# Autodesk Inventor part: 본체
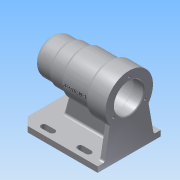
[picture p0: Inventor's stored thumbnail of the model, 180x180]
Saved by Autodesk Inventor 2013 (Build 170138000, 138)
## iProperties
Created: 2017-09
Part Number: 본체
Material: 알루미늄 6061
Document SubType Name: Modeling
Designer: Administrator
Mass: 702.292 g
Surface Area: 713.068 cm^2
Volume: 259.148 cm^3
Density: 2.71 g/cm^3
Author: Administrator
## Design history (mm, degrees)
node "스케치1"
sketch "스케치2"
  geometry: C1 r 34 at (0, 0); 1 further point
  constraints: 1 centre point, 1 coincident
  dimensions: "d15" = 68 diameter of C1
extrude "돌출1" new body sketch "스케치2" distance "d17" = 28; taper "d18" = 0 deg
sketch "스케치3"
  geometry: C1 r 34 at (0, 0) reference; C2 r 30 at (0, 0)
  constraints: 1 centre point, 1 coincident
  dimensions: "d19" = 60 diameter of C2
extrude "돌출2" join sketch "스케치3" distance "d21" = 39; taper "d22" = 0 deg
sketch "스케치4"
  geometry: C1 r 30 at (0, 0) reference; C2 r 27 at (0, 0)
  constraints: 1 centre point, 1 coincident
  dimensions: "d23" = 54 diameter of C2
extrude "돌출3" join sketch "스케치4" distance "d25" = 20; taper "d26" = 0 deg
sketch "스케치5"
  geometry: C1 r 27 at (0, 0) reference; C2 r 25 at (0, 0)
  constraints: 1 centre point, 1 coincident
  dimensions: "d27" = 50 diameter of C2
extrude "돌출4" join sketch "스케치5" distance "d29" = 25; taper "d30" = 0 deg
sketch "스케치6"
  geometry: C1 r 34 at (0, 0) reference; 1 further point
  constraints: 1 coincident
hole "구멍1" sketch "스케치6" at (0, 0) diameter "d31" = 42; stored, may be unused: countersink angle "d35" = 90 deg, drill point angle "d37" = 0 deg; dims "d32" = 6, "d33" = 42, "d34" = 15, "d36" = 15
sketch "스케치7"
  geometry: C1 r 21 at (0, 0) reference
sketch "스케치8"
  geometry: C1 r 21 at (0, 0) reference; C2 r 24 at (0, 0)
  constraints: 2 coincident, 1 centre point
  dimensions: "d38" = 48 diameter of C2
extrude "돌출5" cut sketch "스케치8" distance "d40" = 54; taper "d41" = 0 deg
sketch "스케치9"
  geometry: C1 r 24 at (0, 0) reference; C2 r 21 at (0, 0)
  constraints: 1 centre point, 1 coincident
  dimensions: "d42" = 42 diameter of C2
extrude "돌출6" cut sketch "스케치9" distance "d44" = 12; taper "d45" = 0 deg
sketch "스케치10"
  geometry: C1 r 21 at (0, 0) reference; C2 r 17.5 at (0, 0)
  constraints: 1 centre point, 1 coincident
  dimensions: "d46" = 35 diameter of C2
extrude "돌출7" cut sketch "스케치10" distance "d48" = 18; taper "d49" = 0 deg
sketch "스케치11"
  geometry: C1 r 17.5 at (0, 0) reference; C2 r 16 at (0, 0)
  constraints: 1 centre point, 1 coincident
  dimensions: "d50" = 32 diameter of C2
extrude "돌출8" cut sketch "스케치11" distance "d52" = 4; taper "d53" = 0 deg
sketch "스케치12"
  geometry: C1 r 16 at (0, 0) reference; C2 r 10.5 at (0, 0)
  constraints: 1 centre point, 1 coincident
  dimensions: "d54" = 21 diameter of C2
extrude "돌출9" cut sketch "스케치12" distance "d56" = 3; taper "d57" = 0 deg
node "작업 평면1"
sketch "스케치13"
  geometry: L1 (84, -25)-(84, 25) reference; L2 (-28, 34)-(-28, -34) reference; L3 (84, -45)-(-28, -45); L4 (-28, -45)-(-28, 45); L5 (-28, 45)-(84, 45); L6 (84, 45)-(84, -45); 2 further points
  constraints: 8 end point, 2 midpoint, 2 parallel, 1 horizontal, 1 perpendicular
  dimensions: "d59" = 90 distance between parallel lines of L5 L3; "d61" = 112 distance between parallel lines of L4 L6
extrude "돌출10" join sketch "스케치13" distance "d62" = 8; taper "d63" = 0 deg
sketch "스케치14"
  geometry: L1 (28, -45)-(28, 45) reference; L2 (-8, -30)-(4, -30); L3 (4, -38)-(-8, -38); A1 r 4 centre (-8, -34) between (-8, -30) and (-8, -38); A2 r 4 centre (4, -34) between (4, -38) and (4, -30); 1 further point
  constraints: 4 end point, 4 point on circle, 4 tangent, 2 centre point, 1 horizontal, 1 parallel
  dimensions: "d66" = 12 distance of A2.centre A1.centre; "d68" = 4 radius of A2; "d70" = 24 distance from line of L1 A2.centre; "d71" = 34 vertical distance of point (0, 0) A2.centre
extrude "돌출11" cut sketch "스케치14" stored distance "d72" = 8; taper "d73" = 0 deg
chamfer "모따기1" distance "d77" = 12; stored, may be unused: second distance "d78" = 2, angle "d79" = 45 deg
sketch "스케치15"
  geometry: L1 (90, 0)-(0, 0) reference; L2 (0, 8)-(90, 8) reference; L3 (0, 0)-(0, 8) reference; L4 (17.425, 50.11)-(10, 8); L5 (10, 8)-(80, 8); L6 (45, 70)-(45, 0); L7 (72.575, 50.11)-(80, 8); C1 r 17.5 at (45, 70) reference; C2 r 30 at (45, 70) reference; 1 further point
  constraints: 8 end point, 2 perpendicular, 1 midpoint, 1 point on line, 1 other
  dimensions: "d80" = 10 distance from line of L4.end L3; "d82" = 100 deg angle of L2 L4; "d84" = 50.10971 distance from line of L7.start L1; "d85" = 50.10971 distance from line of L4.start L1
feature "리브1" sketch "스케치15" dims "d86" = 1, "d87" = 8, "d88" = 0, "d89" = 0, "d90" = 1, "d91" = 1
sketch "스케치16"
  geometry: L1 (-84, 33)-(-84, -33) reference; L2 (20, -35)-(20, 35) reference; L3 (20, 4)-(-62, 4); L4 (-62, 4)-(-62, -4); L5 (-62, -4)-(20, -4); L6 (20, -4)-(20, 4); 2 further points
  constraints: 8 end point, 2 midpoint, 2 parallel, 1 horizontal, 1 perpendicular, 1 point on line
  dimensions: "d92" = 8 distance between parallel lines of L5 L3; "d95" = 22 distance between parallel lines of L1 L4
extrude "돌출12" join sketch "스케치16" stored distance "d96" = 8; taper "d97" = 0 deg
feature "면 기울기1" dims angle "d98" = 15 deg
sketch "스케치18"
  geometry: C1 r 21 at (0, 0) reference; C2 r 1 at (0, 26)
  constraints: 1 centre point, 1 vertical alignment
  dimensions: "d102" = 26 distance of C1.centre C2.centre; "d103" = 2 diameter of C2
hole "구멍2" sketch "스케치18" at (0, 26) diameter "d104" = 3.242; stored, may be unused: countersink angle "d108" = 82 deg, drill point angle "d110" = 118 deg; dims "d105" = 8, "d106" = 3.023, "d107" = 15, "d109" = 11
chamfer "모따기2" distance "d114" = 1; stored, may be unused: second distance "d115" = 2, angle "d116" = 45 deg
fillet "모깎기1" dims "d117" = 3
fillet "모깎기2" dims "d118" = 3
fillet "모깎기3" dims "d119" = 0.3
fillet "모깎기4" dims "d120" = 9
fillet "모깎기5" dims "d121" = 3
fillet "모깎기6" dims "d122" = 3
fillet "모깎기7" dims "d123" = 3
fillet "모깎기8" dims "d124" = 3
fillet "모깎기9" dims "d125" = 3
fillet "모깎기10" dims "d126" = 3
node "작업 평면2"
sketch "스케치19"
  geometry: L1 (28, -18.917)-(28, 34) reference; 2 further points
  constraints: 1 horizontal alignment, 1 other
  dimensions: "d128" = 48 distance from line of point (-20, 0) L1
feature "엠보싱1" sketch "스케치19" dims "d29" = 25, "d129" = 0.3, "d130" = 0
node "솔리드1"
pattern_linear "직사각형 패턴1" dims "d76" = 52
mirror "대칭1"
pattern_circular "원형 패턴1" dims angle "d112" = 360 deg
